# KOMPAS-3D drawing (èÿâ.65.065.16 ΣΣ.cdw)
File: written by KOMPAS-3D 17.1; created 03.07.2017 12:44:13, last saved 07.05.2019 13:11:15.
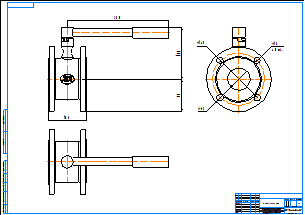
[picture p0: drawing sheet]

Sheet 1: A1, landscape

Title block, sheet 1: name: КШГ.65.065.16 фф; material: Внимание! Данный продукт является объектом авторского права ООО «Торговый Дом АДЛ». / Запрещается изменение, копирование, распространение / (в том числе путем копирования на другие сайты и ресурсы в Интернете) / или любое иное использование информации и объектов без предварительного / согласия правообладателя (ООО «Торговый Дом АДЛ»).; sheets: 1; organisation: ООО "Торговый дом АДЛ"; sheet format: A1; stored path: C:\Users\kka\KOMPAS_Work\!Trash\СС02 СС03 ФФ Смотровые стекла\СС01.cdw

Views: Спереди 1, Проекционный вид 2, Проекционный вид 3
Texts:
  Klimkovich
  ADL
Dimensions and other numbers on the sheet: 280; 144; 106; 90; 145; 63; 18; 4 Отв.; 1:1; 1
